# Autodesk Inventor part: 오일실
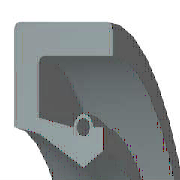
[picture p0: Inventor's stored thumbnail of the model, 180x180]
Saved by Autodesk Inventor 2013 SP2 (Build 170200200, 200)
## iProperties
IsCustomPart: 1
Company: 한국ATC센터
Created: 2014-11
Part Number: 오일실
Material: 고무
Description: 오일-실
Document SubType Name: Modeling
Standard: KS B 2804
Designer: KYOUNG IL JANG
Standards Organization: KS
Language: ko-KR
Size Designation: S - 25 40 8
Categories: <MemberInstance><Categories><Category DisplayName="샤프트 부품" InternalName="7f7aeb1f-a693-4053-b835-cee3144e0d98" Mnemonic="SHFT"><Category DisplayName="실링" Intern
Density: 0.93 g/cm^3
Mass: 2.48215 g
Surface Area: 40.3381 cm^2
Volume: 2.66898 cm^3
Author: KYOUNG IL JANG
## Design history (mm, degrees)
revolve "본체" stored, may be unused: angle "d17" = 90 deg
revolve "스프링1" stored, may be unused: angle "d18" = 90 deg
body "Solid1"
sketch "스케치1"
  geometry: L1 (0, 20)-(8, 20); L2 (8, 20)-(8, 18.75); L3 (8, 18.75)-(1.75, 18.75); L4 (0, 20)-(0, 14.6); L5 (0, 14.6)-(1.75, 14.25); L6 (1.75, 14.25)-(4.9, 12.5); L7 (4.9, 12.5)-(0, 12.5); L8 (6.3, 13.375)-(6.3, 14.6); L9 (0, 0)-(9.586, 0) reference; L10 (4.9, 12.5)-(6.3, 13.375); L11 (0, 18)-(0, -3) reference; L12 (-1.917, 0)-(11.503, 0) reference; L13 (4.2, 14.6)-(1.75, 15.09); L14 (1.75, 15.09)-(1.75, 18.75); L15 (6.3, 14.6)-(5.6, 14.6); C1 r 0.455 at (4.9, 14.6); A1 r 0.7 centre (4.9, 14.6) between (5.6, 14.6) and (4.2, 14.6)
  constraints: 26 end point, 5 horizontal alignment, 4 perpendicular, 2 centre point, 2 collinear, 2 horizontal, 2 parallel, 2 point on circle, 2 point on line, 2 vertical alignment, 1 coincident
  dimensions: "d0" = 40 diameter of L1 L9 (= SD2); "d1" = 26.75 diameter of L8.start L9 (= ABDM); "d2" = 1.25 distance of L1.end L2.end (computed from SD); "d3" = 0.91 diameter of C1 (= SPDI); "d4" = 1.4 diameter of A1 (= SPDA); "d5" = 25 diameter of L6.end L9 (= NND); "d6" = 28.5 diameter of L5.end L9 (= TKDM); "d7" = 29.2 diameter of L4.end L9 (= HLDM); "d8" = 4.9 distance from line of C1.centre L4 (= SPDST); "d9" = 6.3 distance between parallel lines of L8 L4 (= SDI); "d10" = 8 distance between parallel lines of L2 L4 (= SWDT); "d12" = 1.75 distance between parallel lines of L14 L4 (= SD)
fillet "모깎기1" dims "d11" = 0.3 (= RR)
other parameters: "SD2" = 40 [user parameter; used in 1 equation term], "SWDT" = 8 [user parameter; used in 1 equation term], "RR" = 0.3 [user parameter; used in 1 equation term], "SD" = 1.75 [user parameter; used in 2 equation terms], "NND" = 25 [user parameter; used in 1 equation term], "SPDA" = 1.4 [user parameter; used in 1 equation term], "SPDI" = 0.91 [user parameter; used in 1 equation term], "TKDM" = 28.5 [user parameter; used in 1 equation term], "HLDM" = 29.2 [user parameter; used in 1 equation term], "ABDM" = 26.75 [user parameter; used in 1 equation term], "SDI" = 6.3 [user parameter; used in 1 equation term], "SPDST" = 4.9 [user parameter; used in 1 equation term], "d13" = 0, "d14" = 0, "d15" = 0, "LAB" = 0.35 [user parameter]
